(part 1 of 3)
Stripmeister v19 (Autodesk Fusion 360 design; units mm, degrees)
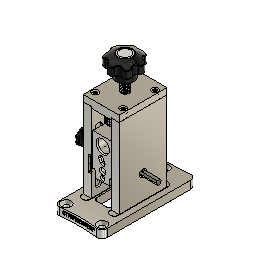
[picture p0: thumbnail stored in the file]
sketch "Sketch1" plane through (0, 0, 0) normal (0, 0, 1) x axis (1, 0, 0)
  line L1 (-38.1, -74.8109) -> (38.1, -74.8109)
  line L2 (-38.1, 74.8109) -> (-38.1, -74.8109)
  line L3 (38.1, 74.8109) -> (-38.1, 74.8109)
  line L4 (38.1, -74.8109) -> (38.1, 74.8109)
  line L5 (-38.1, 74.8109) -> (38.1, -74.8109)
  line L6 (38.1, 74.8109) -> (-38.1, -74.8109)
  line L7 (0, -74.8109) -> (0, 74.8109)
  line L8 (22.225, -74.8109) -> (22.225, 74.8109)
  line L9 (22.225, 0) -> (0, 0)
  line L10 (15.621, -39.4335) -> (15.621, 39.4335)
  line L11 (28.829, 39.4335) -> (28.829, -39.4335)
  line L12 (22.225, -46.0375) -> (22.225, 46.0375)
  line L13 (16.6687, -29.3687) -> (16.6688, 29.3687)
  line L14 (27.7813, 29.3687) -> (27.7813, -29.3688)
  line L15 (22.225, -34.925) -> (22.225, 34.925)
  line L16 (-28.829, 39.4335) -> (-28.829, -39.4335)
  line L17 (-27.7813, 29.3688) -> (-27.7813, -29.3688)
  line L18 (-16.6687, -29.3687) -> (-16.6688, 29.3687)
  line L19 (-15.621, -39.4335) -> (-15.621, 39.4335)
  line L20 (-12.7, 4.1513) -> (12.7, 4.1513)
  line L21 (-12.7, -37.5047) -> (-12.7, 4.1513)
  line L22 (12.7, -37.5047) -> (-12.7, -37.5047)
  line L23 (12.7, 4.1513) -> (12.7, -37.5047)
  line L24 (-12.7, -37.5047) -> (12.7, 4.1513)
  line L25 (12.7, -37.5047) -> (-12.7, 4.1513)
  line L26 (5.08, 10.8982) -> (0, 10.8982)
  line L27 (-3.175, 8.5169) -> (3.175, 8.5169)
  line L28 (-6.35, 18.0419) -> (-6.35, 11.6919)
  line L29 (3.175, 21.2169) -> (-3.175, 21.2169)
  line L30 (6.35, 11.6919) -> (6.35, 18.0419)
  line L31 (-6.35, 21.2169) -> (6.35, 8.5169)
  line L32 (6.35, 21.2169) -> (-6.35, 8.5169)
  circle C1 centre (22.225, 25.4) radius 3.9687
  circle C2 centre (22.225, -25.4) radius 3.9687
  circle C3 centre (-22.225, 25.4) radius 3.9687
  circle C4 centre (-22.225, -25.4) radius 3.9687
  arc A1 centre (22.225, -39.4335) radius 6.604 clockwise from (28.829, -39.4335) to (15.621, -39.4335)
  arc A2 centre (22.225, 39.4335) radius 6.604 clockwise from (15.621, 39.4335) to (28.829, 39.4335)
  arc A3 centre (22.225, -29.3688) radius 5.5563 clockwise from (27.7813, -29.3688) to (16.6687, -29.3687)
  arc A4 centre (22.225, 29.3687) radius 5.5563 clockwise from (16.6688, 29.3687) to (27.7813, 29.3687)
  arc A5 centre (-22.225, 39.4335) radius 6.604 clockwise from (-28.829, 39.4335) to (-15.621, 39.4335)
  arc A6 centre (-22.225, 29.3687) radius 5.5562 clockwise from (-27.7813, 29.3688) to (-16.6688, 29.3687)
  arc A7 centre (-22.225, -39.4335) radius 6.604 clockwise from (-15.621, -39.4335) to (-28.829, -39.4335)
  arc A8 centre (-22.225, -29.3688) radius 5.5562 clockwise from (-16.6687, -29.3687) to (-27.7813, -29.3688)
  circle C5 centre (-22.225, -25.4) radius 3.9687
  circle C6 centre (-22.225, 25.4) radius 3.9687
  circle C7 centre (28.575, 65.2859) radius 4.7625
  circle C8 centre (-28.575, 65.2859) radius 4.7625
  circle C9 centre (28.575, -65.2859) radius 3.9687
  circle C10 centre (-28.575, -65.2859) radius 3.9687
  circle C11 centre (0, 14.8669) radius 3.9688
  arc A9 centre (3.175, 11.6919) radius 3.175 clockwise from (6.35, 11.6919) to (3.175, 8.5169)
  arc A10 centre (-3.175, 11.6919) radius 3.175 clockwise from (-3.175, 8.5169) to (-6.35, 11.6919)
  arc A11 centre (-3.175, 18.0419) radius 3.175 clockwise from (-6.35, 18.0419) to (-3.175, 21.2169)
  arc A12 centre (3.175, 18.0419) radius 3.175 clockwise from (3.175, 21.2169) to (6.35, 18.0419)
  circle C12 centre (0, 62.4919) radius 3.9687
  point P6 (0, 0)
  point P1 (0, 0)
  point P7 (0, 74.8109)
  point P8 (0, -74.8109)
  point P9 (22.225, 74.8109)
  point P10 (22.225, -74.8109)
  point P11 (22.225, 25.4)
  point P12 (22.225, -25.4)
  point P13 (0, 0)
  point P14 (22.225, 0)
  point P23 (22.225, 46.0375)
  point P24 (22.225, -46.0375)
  point P31 (22.225, 34.925)
  point P32 (22.225, -34.925)
  point P17 (15.621, 39.4335)
  point P35 (-15.621, 39.4335)
  point P18 (15.621, -39.4335)
  point P42 (-15.621, -39.4335)
  point P19 (28.829, -39.4335)
  point P36 (-28.829, -39.4335)
  point P20 (28.829, 39.4335)
  point P34 (-28.829, 39.4335)
  point P25 (16.6688, 29.3687)
  point P40 (-16.6688, 29.3687)
  point P26 (16.6687, -29.3687)
  point P41 (-16.6687, -29.3687)
  point P27 (27.7813, -29.3688)
  point P37 (-27.7813, -29.3688)
  point P28 (27.7813, 29.3687)
  point P38 (-27.7813, 29.3688)
  point P51 (0, -16.6767)
  point P56 (0, 10.8982)
  point P58 (0, 14.8669)
  point P63 (0, 14.8669)
  point P59 (6.35, 8.5169)
  point P60 (-6.35, 8.5169)
  point P61 (-6.35, 21.2169)
  point P62 (6.35, 21.2169)
  point P76 (0, 62.4919)
  point P4 (-38.1, 74.8109)
  point P5 (38.1, 74.8109)
  point P3 (-38.1, -74.8109)
  point P49 (-12.7, -37.5047)
  point P50 (12.7, -37.5047)
  point P48 (-12.7, 4.1513)
  point P54 (28.575, -65.2859)
  point P52 (28.575, 65.2859)
  horizontal L1
  perpendicular L1 L2
  parallel L1 L3
  parallel L2 L4
  coincident L5 P6
  coincident L6 P6
  coincident P1 P6
  midpoint L3 P7
  midpoint L1 P8
  coincident L3 P9
  coincident L1 P10
  perpendicular L1 L8
  coincident L8 P11
  coincident L8 P12
  coincident P1 P13
  midpoint L8 P14
  symmetric L7 C1 C3
  symmetric L7 C2 C4
  tangent L10 A1
  tangent A1 L11
  parallel L10 L11
  tangent L11 A2
  tangent L10 A2
  midpoint A2 P23
  midpoint A1 P24
  coincident L8 P24
  parallel L8 L12
  midpoint P14 L12
  tangent L13 A3
  tangent A3 L14
  parallel L13 L14
  tangent L14 A4
  tangent L13 A4
  midpoint A4 P31
  midpoint A3 P32
  parallel L12 L15
  coincident L12 P31
  midpoint P14 L15
  symmetric L7 C1 C6
  symmetric L7 C2 C5
  symmetric L7 P17 P35
  symmetric L7 P18 P42
  symmetric L7 P19 P36
  symmetric L7 P20 P34
  symmetric L7 A1 A7
  symmetric L7 A2 A5
  symmetric L7 P25 P40
  symmetric L7 P26 P41
  symmetric L7 P27 P37
  symmetric L7 P28 P38
  symmetric L7 A3 A8
  symmetric L7 A4 A6
  horizontal L20
  perpendicular L20 L21
  parallel L20 L22
  parallel L21 L23
  coincident L24 P51
  coincident L25 P51
  coincident L7 P51
  symmetric L7 C7 C8
  symmetric L7 C9 C10
  coincident L7 P56
  perpendicular L7 L26
  coincident L7 P58
  tangent L26 C11
  horizontal L27
  perpendicular L27 L28
  parallel L27 L29
  parallel L28 L30
  coincident L31 P63
  coincident L32 P63
  coincident P58 P63
  coincident P59 L30
  coincident P59 L27
  tangent L30 A9
  tangent L27 A9
  coincident P60 L27
  coincident P60 L28
  tangent L27 A10
  tangent L28 A10
  equal A9 A10
  coincident P61 L28
  coincident P61 L29
  tangent L28 A11
  tangent L29 A11
  equal A9 A11
  coincident P62 L29
  coincident P62 L30
  tangent L29 A12
  tangent L30 A12
  equal A9 A12
  coincident L7 P76
  dimension "d1" distance P4 P5 = 76.2
  dimension "d2" distance P3 P4 = 149.6219 (= "5 57/64")
  dimension "d3" diameter C1 = 7.9375 (= "( 5 / 16 ) * 1 in")
  dimension "d4" diameter C2 = 7.9375 (= "( 5 / 16 ) * 1 in")
  dimension "d5" distance P11 L9 = 25.4
  dimension "d6" distance P12 L9 = 25.4
  dimension "d7" distance L7 P11 = 22.225 (= "( 1.75 / 2 ) * 1 in")
  dimension "d8" diameter A1 = 13.208
  dimension "d9" distance P23 P24 = 92.075
  dimension "d10" distance P31 P32 = 69.85
  dimension "d11" diameter A3 = 11.1125
  dimension "d12" distance P49 P50 = 25.4
  dimension "d13" distance P48 P49 = 41.656
  dimension "d14" distance L1 L22 = 37.3062 (= "1 15/32")
  dimension "d16" diameter C7 = 9.525 (= "( 3 / 8 ) * 1 in")
  dimension "d17" diameter C9 = 7.9375
  dimension "d18" distance L4 P54 = 9.525 (= "( 3 / 8 ) * 1 in")
  dimension "d19" distance L1 P54 = 9.525 (= "( 3 / 8 ) * 1 in")
  dimension "d20" distance L3 P52 = 9.525 (= "( 3 / 8 ) * 1 in")
  dimension "d21" distance L4 P52 = 9.525 (= "( 3 / 8 ) * 1 in")
  dimension "d22" distance L20 L26 = 6.7469 (= "( 17 / 64 ) * 1 in")
  dimension "d23" diameter C11 = 7.9375 (= "( 5 / 16 ) * 1 in")
  dimension "d24" distance P61 P62 = 12.7
  dimension "d25" distance P60 P61 = 12.7
  dimension "d26" radius A9 = 3.175
  dimension "d27" diameter C12 = 7.9375 (= "( 5 / 16 ) * 1 in")
  dimension "d28" distance P58 P76 = 47.625 (= "1 7/8")
extrude "Extrude1" new body sketch "Sketch1" profile of L1 L2 L3 L4 C1 C2 C3 C4 L10 A1 L11 A2 L13 A3 L14 A4 A5 L16 L17 A6 L18 L19 A7 A8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 against normal blind 12.7
extrude "Extrude2" cut sketch "Sketch1" profile of C1 C2 C3 C4 L13 A3 L14 A4 L17 A6 L18 A8 C5 C6 against normal blind 2.3813 (magnitude of "( -3 / 32 ) * 1 in")
extrude "Extrude3" cut sketch "Sketch1" profile of L10 A1 L11 A2 L13 A3 L14 A4 A5 L16 L17 A6 L18 L19 A7 A8 against normal blind 0.3969 (magnitude of "( -1 / 64 ) * 1 in")
chamfer "Chamfer1" distance 3.81
extrude "Extrude4" cut sketch "Sketch1" profile of C11 L27 L28 L29 L30 A9 A10 A11 A12 against normal blind 4.3656 (magnitude of "( -11 / 64 ) * 1 in")
fillet "Fillet1" radius 7.9375 (= "( 5 / 16 ) * 1 in")
fillet "Fillet2" radius 4.7625
sketch "Sketch1" plane through (0, 0, 0) normal (0, 0, 1) x axis (-1, 0, 0)
  line L1 (-6.35, -11.6919) -> (-6.35, -18.0419)
  line L2 (3.175, -8.5169) -> (-3.175, -8.5169)
  line L3 (6.35, -18.0419) -> (6.35, -11.6919)
  line L4 (-3.175, -21.2169) -> (3.175, -21.2169)
  line L5 (38.1, 66.8734) -> (38.1, -66.8734)
  line L6 (-30.1625, 74.8109) -> (30.1625, 74.8109)
  line L7 (-38.1, -66.8734) -> (-38.1, 66.8734)
  line L8 (30.1625, -74.8109) -> (-30.1625, -74.8109)
  line L9 (-12.7, 32.7422) -> (-12.7, 0.6112)
  line L10 (7.9375, 37.5047) -> (-7.9375, 37.5047)
  line L11 (12.7, 0.6112) -> (12.7, 32.7422)
  line L12 (-7.9375, -4.1513) -> (7.9375, -4.1513)
  line L13 (-15.621, -39.4335) -> (-15.621, 39.4335)
  line L14 (-28.829, 39.4335) -> (-28.829, -39.4335)
  line L15 (28.829, -39.4335) -> (28.829, 39.4335)
  line L16 (15.621, 39.4335) -> (15.621, -39.4335)
  line L17 (-6.35, -18.0419) -> (-6.35, -11.6919)
  line L18 (3.175, -21.2169) -> (-3.175, -21.2169)
  line L19 (6.35, -11.6919) -> (6.35, -18.0419)
  line L20 (-3.175, -8.5169) -> (3.175, -8.5169)
  arc A1 centre (-3.175, -11.6919) radius 3.175 clockwise from (-6.35, -11.6919) to (-3.175, -8.5169)
  arc A2 centre (3.175, -11.6919) radius 3.175 clockwise from (3.175, -8.5169) to (6.35, -11.6919)
  arc A3 centre (3.175, -18.0419) radius 3.175 clockwise from (6.35, -18.0419) to (3.175, -21.2169)
  arc A4 centre (-3.175, -18.0419) radius 3.175 clockwise from (-3.175, -21.2169) to (-6.35, -18.0419)
  circle C1 centre (-28.575, 65.2859) radius 7.7787
  arc A5 centre (30.1625, -66.8734) radius 7.9375 clockwise from (38.1, -66.8734) to (30.1625, -74.8109)
  arc A6 centre (30.1625, 66.8734) radius 7.9375 clockwise from (30.1625, 74.8109) to (38.1, 66.8734)
  arc A7 centre (-30.1625, 66.8734) radius 7.9375 clockwise from (-38.1, 66.8734) to (-30.1625, 74.8109)
  arc A8 centre (-30.1625, -66.8734) radius 7.9375 clockwise from (-30.1625, -74.8109) to (-38.1, -66.8734)
  arc A9 centre (-7.9375, 32.7422) radius 4.7625 clockwise from (-12.7, 32.7422) to (-7.9375, 37.5047)
  arc A10 centre (7.9375, 32.7422) radius 4.7625 clockwise from (7.9375, 37.5047) to (12.7, 32.7422)
  arc A11 centre (7.9375, 0.6112) radius 4.7625 clockwise from (12.7, 0.6112) to (7.9375, -4.1513)
  arc A12 centre (-7.9375, 0.6112) radius 4.7625 clockwise from (-7.9375, -4.1513) to (-12.7, 0.6112)
  arc A13 centre (-22.225, -39.4335) radius 6.604 clockwise from (-15.621, -39.4335) to (-28.829, -39.4335)
  arc A14 centre (-22.225, 39.4335) radius 6.604 clockwise from (-28.829, 39.4335) to (-15.621, 39.4335)
  arc A15 centre (22.225, -39.4335) radius 6.604 clockwise from (28.829, -39.4335) to (15.621, -39.4335)
  arc A16 centre (22.225, 39.4335) radius 6.604 clockwise from (15.621, 39.4335) to (28.829, 39.4335)
  circle C2 centre (0, -62.4919) radius 7.7787
  circle C3 centre (28.575, 65.2859) radius 7.7787
  circle C4 centre (0, -14.8669) radius 3.9687
  arc A17 centre (-3.175, -11.6919) radius 3.175 clockwise from (-6.35, -11.6919) to (-3.175, -8.5169)
  arc A18 centre (-3.175, -18.0419) radius 3.175 clockwise from (-3.175, -21.2169) to (-6.35, -18.0419)
  arc A19 centre (3.175, -18.0419) radius 3.175 clockwise from (6.35, -18.0419) to (3.175, -21.2169)
  arc A20 centre (3.175, -11.6919) radius 3.175 clockwise from (3.175, -8.5169) to (6.35, -11.6919)
  circle C5 centre (0, -14.8669) radius 9.3266
  concentric C4 C5
  dimension "d42" diameter C5 = 18.6531 (= "( 47 / 64 ) * 1 in")
extrude "Extrude1" new body sketch "Sketch1" profile of L1 A1 L2 A2 L3 A3 L4 A4 C4 A17 L17 A18 L18 A19 L19 A20 L20 to an object
extrude "Extrude2" add sketch "Sketch1" profile of L1 A1 L2 A2 L3 A3 L4 A4 C4 A17 L17 A18 L18 A19 L19 A20 L20 C5 along normal blind 38.608
extrude "Extrude3" add sketch "Sketch1" profile of C4 against normal blind 4.3688
extrude "Extrude4" cut of existing geometry blind 0
extrude "Extrude5" add sketch "Sketch1" profile of L1 A1 L2 A2 L3 A3 L4 A4 C4 A17 L17 A18 L18 A19 L19 A20 L20 against normal blind 4.3688
extrude "Extrude6" sketch "Sketch1" profile of C4 blind 15.875 (= "( 5 / 8 ) * 1 in")
sketch "Sketch2" plane through (0, 0, 38.608) normal (0, 0, 1) x axis (-1, 0, 0)
  line L1 (-9.144, -16.7032) -> (9.144, -16.7032)
  line L2 (0, -5.5404) -> (0, -16.7032)
  circle C1 centre (0, -14.8669) radius 9.3266
  arc A1 centre (-16.0599, -1.7116) radius 16.51 clockwise from (0, -5.5404) to (-9.144, -16.7032)
  arc A2 centre (16.0599, -1.7116) radius 16.51 clockwise from (9.144, -16.7032) to (0, -5.5404)
  point P3 (9.144, -16.7032)
  point P4 (-9.144, -16.7032)
  point P5 (0, -16.7032)
  point P6 (0, -5.5404)
  point P9 (9.144, -16.7032)
  point P10 (0, -5.5404)
  coincident C1 P3
  coincident C1 P4
  horizontal L1
  midpoint L1 P5
  coincident C1 P6
  perpendicular L1 L2
  symmetric P4 L2 P9
  symmetric P6 L2 P10
  symmetric L2 A1 A2
  dimension "d57" distance P3 P4 = 18.288
  dimension "d58" radius A1 = 16.51
extrude "Extrude7" cut sketch "Sketch2" profile of C1 A1 A2 against normal blind 12.7
sketch "Sketch3" plane through (0, 0, 38.608) normal (0, 0, 1) x axis (-1, 0, 0)
  arc A1 centre (16.0599, -1.7116) radius 16.51 clockwise from (9.144, -16.7032) to (0, -5.5404)
  arc A2 centre (-16.0599, -1.7116) radius 16.51 clockwise from (0, -5.5404) to (-9.144, -16.7032)
  arc A3 centre (0, -14.8669) radius 9.3266 clockwise from (9.144, -16.7032) to (-9.144, -16.7032)
  arc A4 centre (0, -14.8669) radius 9.3266 clockwise from (9.144, -16.7032) to (-9.144, -16.7032)
  arc A5 centre (0, -14.8669) radius 9.3266 clockwise from (-9.144, -16.7032) to (0, -5.5404)
  arc A6 centre (0, -14.8669) radius 9.3266 clockwise from (0, -5.5404) to (9.144, -16.7032)
  circle C1 centre (0, -14.8669) radius 9.3266
  arc A7 centre (0, -14.8669) radius 9.1996 clockwise from (9.0195, -16.6782) to (-9.0195, -16.6782)
  arc A8 centre (0, -14.8669) radius 9.1996 clockwise from (0, -5.6674) to (9.0195, -16.6782)
  arc A9 centre (0, -14.8669) radius 9.1996 clockwise from (-9.0195, -16.6782) to (0, -5.6674)
  dimension "d61" = -0.127
extrude "Extrude8" cut sketch "Sketch3" blind -0.635 from offset -20.9677
fillet "Fillet1" radius 0.254
thread "Thread1"
sketch "Sketch2" plane through (0, 0, -12.7) normal (0, 0, -1) x axis (1, 0, 0)
  line L1 (30.1625, -74.8109) -> (-30.1625, -74.8109)
  line L2 (38.1, 66.8734) -> (38.1, -66.8734)
  line L3 (-30.1625, 74.8109) -> (30.1625, 74.8109)
  line L4 (-38.1, -66.8734) -> (-38.1, 66.8734)
  line L5 (12.7, 0.6112) -> (12.7, 32.7422)
  line L6 (-7.9375, -4.1513) -> (7.9375, -4.1513)
  line L7 (-12.7, 32.7422) -> (-12.7, 0.6112)
  line L8 (7.9375, 37.5047) -> (-7.9375, 37.5047)
  arc A1 centre (-30.1625, -66.8734) radius 7.9375 clockwise from (-30.1625, -74.8109) to (-38.1, -66.8734)
  arc A2 centre (30.1625, -66.8734) radius 7.9375 clockwise from (38.1, -66.8734) to (30.1625, -74.8109)
  arc A3 centre (30.1625, 66.8734) radius 7.9375 clockwise from (30.1625, 74.8109) to (38.1, 66.8734)
  arc A4 centre (-30.1625, 66.8734) radius 7.9375 clockwise from (-38.1, 66.8734) to (-30.1625, 74.8109)
  circle C1 centre (-22.225, -25.4) radius 3.9687
  circle C2 centre (28.575, 65.2859) radius 3.9687
  circle C3 centre (-22.225, 25.4) radius 3.9687
  circle C4 centre (0, -14.8669) radius 3.9687
  circle C5 centre (-28.575, 65.2859) radius 3.9687
  circle C6 centre (0, -62.4919) radius 3.9687
  circle C7 centre (22.225, -25.4) radius 3.9688
  circle C8 centre (22.225, 25.4) radius 3.9687
  arc A5 centre (7.9375, 0.6112) radius 4.7625 clockwise from (12.7, 0.6112) to (7.9375, -4.1513)
  arc A6 centre (-7.9375, 0.6112) radius 4.7625 clockwise from (-7.9375, -4.1513) to (-12.7, 0.6112)
  arc A7 centre (-7.9375, 32.7422) radius 4.7625 clockwise from (-12.7, 32.7422) to (-7.9375, 37.5047)
  arc A8 centre (7.9375, 32.7422) radius 4.7625 clockwise from (7.9375, 37.5047) to (12.7, 32.7422)
  circle C9 centre (22.225, 25.4) radius 5.1594
  circle C10 centre (22.225, -25.4) radius 5.1594
  circle C11 centre (-22.225, -25.4) radius 5.1594
  circle C12 centre (-22.225, 25.4) radius 5.1594
  circle C13 centre (0, -14.8669) radius 5.1594
  concentric C8 C9
  concentric C7 C10
  concentric C1 C11
  concentric C3 C12
  concentric C4 C13
  dimension "d67" diameter C9 = 10.3188 (= "( 13 / 32 ) * 1 in")
  dimension "d68" diameter C10 = 10.3188 (= "( 13 / 32 ) * 1 in")
  dimension "d69" diameter C11 = 10.3188 (= "( 13 / 32 ) * 1 in")
  dimension "d70" diameter C12 = 10.3188 (= "( 13 / 32 ) * 1 in")
  dimension "d71" diameter C13 = 10.3188 (= "( 13 / 32 ) * 1 in")
extrude "Extrude5" cut sketch "Sketch2" profile of C1 C3 C4 C7 C8 C9 C10 C11 C12 C13 against normal blind 4.7625 (magnitude of "( -3 / 16 ) * 1 in")
base_feature "Base Feature1"
position "Position1"
copy_paste_bodies "CopyPasteBodies1"
move "Move1"
copy_paste_bodies "CopyPasteBodies2"
move "Move2"
copy_paste_bodies "CopyPasteBodies3"
move "Move3"
align "Align1"
align "Align2"
align "Align3"
align "Align4"
sketch "Sketch1" plane through (0, 0, 0) normal (0, 0, 1) x axis (-1, 0, 0)
  line L1 (-6.35, -11.6919) -> (-6.35, -18.0419)
  line L2 (3.175, -8.5169) -> (-3.175, -8.5169)
  line L3 (6.35, -18.0419) -> (6.35, -11.6919)
  line L4 (-3.175, -21.2169) -> (3.175, -21.2169)
  line L5 (38.1, 66.8734) -> (38.1, -66.8734)
  line L6 (-30.1625, 74.8109) -> (30.1625, 74.8109)
  line L7 (-38.1, -66.8734) -> (-38.1, 66.8734)
  line L8 (30.1625, -74.8109) -> (-30.1625, -74.8109)
  line L9 (-12.7, 32.7422) -> (-12.7, 0.6112)
  line L10 (7.9375, 37.5047) -> (-7.9375, 37.5047)
  line L11 (12.7, 0.6112) -> (12.7, 32.7422)
  line L12 (-7.9375, -4.1513) -> (7.9375, -4.1513)
  line L13 (-15.621, -39.4335) -> (-15.621, 39.4335)
  line L14 (-28.829, 39.4335) -> (-28.829, -39.4335)
  line L15 (28.829, -39.4335) -> (28.829, 39.4335)
  line L16 (15.621, 39.4335) -> (15.621, -39.4335)
  line L17 (27.7813, 29.3688) -> (27.7813, -29.3687)
  line L18 (16.6688, -29.3687) -> (16.6688, 29.3687)
  line L19 (22.225, -25.4) -> (22.225, 25.4)
  line L20 (15.875, -38.1) -> (28.575, -38.1)
  line L21 (15.875, 38.1) -> (15.875, -38.1)
  line L22 (28.575, 38.1) -> (15.875, 38.1)
  line L23 (28.575, -38.1) -> (28.575, 38.1)
  line L24 (15.875, 38.1) -> (28.575, -38.1)
  line L25 (28.575, 38.1) -> (15.875, -38.1)
  arc A1 centre (-3.175, -11.6919) radius 3.175 clockwise from (-6.35, -11.6919) to (-3.175, -8.5169)
  arc A2 centre (3.175, -11.6919) radius 3.175 clockwise from (3.175, -8.5169) to (6.35, -11.6919)
  arc A3 centre (3.175, -18.0419) radius 3.175 clockwise from (6.35, -18.0419) to (3.175, -21.2169)
  arc A4 centre (-3.175, -18.0419) radius 3.175 clockwise from (-3.175, -21.2169) to (-6.35, -18.0419)
  circle C1 centre (-28.575, 65.2859) radius 7.7787
  arc A5 centre (30.1625, -66.8734) radius 7.9375 clockwise from (38.1, -66.8734) to (30.1625, -74.8109)
  arc A6 centre (30.1625, 66.8734) radius 7.9375 clockwise from (30.1625, 74.8109) to (38.1, 66.8734)
  arc A7 centre (-30.1625, 66.8734) radius 7.9375 clockwise from (-38.1, 66.8734) to (-30.1625, 74.8109)
  arc A8 centre (-30.1625, -66.8734) radius 7.9375 clockwise from (-30.1625, -74.8109) to (-38.1, -66.8734)
  arc A9 centre (-7.9375, 32.7422) radius 4.7625 clockwise from (-12.7, 32.7422) to (-7.9375, 37.5047)
  arc A10 centre (7.9375, 32.7422) radius 4.7625 clockwise from (7.9375, 37.5047) to (12.7, 32.7422)
  arc A11 centre (7.9375, 0.6112) radius 4.7625 clockwise from (12.7, 0.6112) to (7.9375, -4.1513)
  arc A12 centre (-7.9375, 0.6112) radius 4.7625 clockwise from (-7.9375, -4.1513) to (-12.7, 0.6112)
  arc A13 centre (-22.225, -39.4335) radius 6.604 clockwise from (-15.621, -39.4335) to (-28.829, -39.4335)
  arc A14 centre (-22.225, 39.4335) radius 6.604 clockwise from (-28.829, 39.4335) to (-15.621, 39.4335)
  arc A15 centre (22.225, -39.4335) radius 6.604 clockwise from (28.829, -39.4335) to (15.621, -39.4335)
  arc A16 centre (22.225, 39.4335) radius 6.604 clockwise from (15.621, 39.4335) to (28.829, 39.4335)
  circle C2 centre (0, -62.4919) radius 7.7787
  circle C3 centre (28.575, 65.2859) radius 7.7787
  circle C4 centre (22.225, -25.4) radius 3.9687
  circle C5 centre (22.225, 25.4) radius 3.9687
  arc A17 centre (22.225, -29.3687) radius 5.5562 clockwise from (27.7813, -29.3687) to (16.6688, -29.3687)
  arc A18 centre (22.225, 29.3688) radius 5.5562 clockwise from (16.6688, 29.3687) to (27.7813, 29.3688)
  point P54 (22.225, 25.4)
  point P61 (22.225, 25.4)
  point P53 (22.225, -25.4)
  point P62 (22.225, -25.4)
  point P67 (22.225, 0)
  point P65 (15.875, 38.1)
  point P66 (28.575, 38.1)
  point P64 (15.875, -38.1)
  coincident P54 P61
  coincident P53 P62
  horizontal L20
  perpendicular L20 L21
  parallel L20 L22
  parallel L21 L23
  coincident L24 P67
  coincident L25 P67
  midpoint L19 P67
  dimension "d74" distance P65 P66 = 12.7
  dimension "d75" distance P64 P65 = 76.2
extrude "Extrude1" new body sketch "Sketch1" profile of C4 C5 A17 L17 A18 L18 to an object
extrude "Extrude2" add sketch "Sketch1" profile of C4 C5 A17 L17 A18 L18 L20 L21 L22 L23 along normal blind 127
extrude "Extrude3" cut sketch "Sketch1" profile of C4 C5 along normal blind 16.129
sketch "Sketch2" plane through (0, 0, 127) normal (0, 0, 1) x axis (-1, 0, 0)
  line L1 (15.875, 38.1) -> (28.575, 38.1)
  line L2 (15.875, -38.1) -> (15.875, 38.1)
  line L3 (28.575, -38.1) -> (15.875, -38.1)
  line L4 (28.575, 38.1) -> (28.575, -38.1)
  circle C1 centre (22.225, 25.4) radius 3.9687
  circle C2 centre (22.225, -25.4) radius 3.9687
  circle C3 centre (22.225, -25.4) radius 5.5245
  circle C4 centre (22.225, 25.4) radius 5.5245
  concentric C2 C3
  concentric C1 C4
  dimension "d83" diameter C3 = 11.049
  dimension "d84" diameter C4 = 11.049
extrude "Extrude4" add sketch "Sketch2" profile of C1 C2 C3 C4 along normal blind 1.778
extrude "Extrude5" of existing geometry blind -16.129
thread "Thread1"
fillet "Fillet1" radius 1.27
align "Align1"
sketch "Sketch3" plane through (15.875, 0, 0) normal (-1, 0, 0) x axis (0, -1, 0)
  line L1 (38.1, 0) -> (-38.1, 0)
  line L2 (38.1, 127) -> (38.1, 0)
  line L3 (-38.1, 127) -> (38.1, 127)
  line L4 (-38.1, 0) -> (-38.1, 127)
  line L5 (20.574, 15.748) -> (20.574, 93.472)
  line L6 (31.75, 93.472) -> (31.75, 15.748)
  line L7 (26.162, 10.16) -> (26.162, 99.06)
  line L8 (38.1, 52.6923) -> (-38.1, 52.6923)
  line L9 (0, 52.6923) -> (0, 127)
  line L10 (5.588, 58.2803) -> (0, 58.2803)
  line L11 (-5.588, 58.2803) -> (0, 58.2803)
  line L12 (-5.588, 127) -> (-5.588, 58.2803)
  line L13 (5.588, 127) -> (5.588, 58.2803)
  line L14 (6.096, 127) -> (-6.096, 127)
  line L15 (5.588, 116.84) -> (-5.588, 116.84)
  line L16 (-5.588, 116.84) -> (-6.096, 127)
  line L17 (5.588, 116.84) -> (6.096, 127)
  line L18 (0, 0) -> (0, 58.2803)
  line L19 (0, 10.16) -> (38.1, 10.16)
  arc A1 centre (26.162, 15.748) radius 5.588 clockwise from (31.75, 15.748) to (20.574, 15.748)
  arc A2 centre (26.162, 93.472) radius 5.588 clockwise from (20.574, 93.472) to (31.75, 93.472)
  circle C1 centre (0, 58.2803) radius 5.588
  circle C2 centre (0, 38.1) radius 11.43
  circle C3 centre (0, 38.1) radius 5.8674
  point P12 (26.162, 99.06)
  point P13 (26.162, 10.16)
  point P14 (-38.1, 52.6923)
  point P15 (38.1, 52.6923)
  point P16 (0, 127)
  point P17 (0, 52.6923)
  point P18 (0, 58.2803)
  point P19 (0, 58.2803)
  point P20 (5.588, 58.2803)
  point P21 (0, 58.2803)
  point P22 (-5.588, 58.2803)
  point P23 (-5.588, 127)
  point P24 (5.588, 127)
  point P27 (-5.588, 116.84)
  point P28 (5.588, 116.84)
  point P29 (0, 58.2803)
  point P1 (0, 0)
  point P30 (0, 0)
  point P31 (0, 38.1)
  point P32 (38.1, 10.16)
  point P33 (0, 10.16)
  point P25 (-6.096, 127)
  point P26 (6.096, 127)
  tangent L5 A1
  tangent A1 L6
  parallel L5 L6
  tangent L6 A2
  tangent L5 A2
  midpoint A2 P12
  midpoint A1 P13
  parallel L2 L7
  coincident L4 P14
  coincident L2 P15
  perpendicular L2 L8
  midpoint L3 P16
  midpoint L8 P17
  coincident L9 P18
  tangent L8 C1
  coincident P18 P19
  coincident C1 P20
  perpendicular L9 L10
  coincident P18 P21
  coincident C1 P22
  perpendicular L9 L11
  coincident L3 P23
  tangent C1 L12
  coincident L3 P24
  tangent C1 L13
  perpendicular L13 L14
  midpoint P16 L14
  coincident L12 P27
  coincident L13 P28
  perpendicular L13 L15
  coincident P18 P29
  coincident P1 P30
  coincident L18 P31
  coincident L2 P32
  coincident L18 P33
  perpendicular L18 L19
  tangent A1 L19
  concentric C2 C3
  dimension "d92" diameter A1 = 11.176
  dimension "d93" distance L3 L8 = 74.3077
  dimension "d94" diameter C1 = 11.176
  dimension "d95" distance P25 P26 = 12.192
  dimension "d96" distance L14 L15 = 10.16
  dimension "d97" distance P1 P31 = 38.1
  dimension "d98" diameter C2 = 22.86
  dimension "d99" distance L2 L6 = 6.35
  dimension "d100" distance L1 L19 = 10.16
  dimension "d101" diameter C3 = 11.7348
extrude "Extrude6" cut sketch "Sketch3" profile of L3 L5 A1 L6 A2 C1 L12 L13 L16 L17 against normal blind 3.175 (magnitude of "( -1 / 8 ) * 1 in")
extrude "Extrude7" cut sketch "Sketch3" profile of C3 against normal blind 12.7
extrude "Extrude8" cut sketch "Sketch3" profile of C2 C3 against normal blind 7.9375
fillet "Fillet2" radius 1.27
mirror "Mirror1" mirrorStitchTolerance 0.1016
copy_paste_bodies "CutPasteBodies"
component_from_bodies "Body->Comp"
delete_face "DeleteFace1"
base_feature "Base Feature1"
offset_faces "OffsetFaces1" distance 0.381
base_feature "Base Feature1"
position "Position2"
position "Position3"
sketch "Sketch1" plane through (-15.875, 0, 0) normal (1, 0, 0) x axis (0, 1, 0)
  line L1 (5.588, 116.84) -> (6.0357, 125.7934)
  line L2 (5.588, 58.2803) -> (5.588, 116.84)
  line L3 (-5.588, 116.84) -> (-5.588, 58.2803)
  line L4 (-6.0357, 125.7934) -> (-5.588, 116.84)
  line L5 (-38.1, 127) -> (-7.3041, 127)
  line L6 (-38.1, 0) -> (-38.1, 127)
  line L7 (38.1, 0) -> (-38.1, 0)
  line L8 (38.1, 127) -> (38.1, 0)
  line L9 (7.3041, 127) -> (38.1, 127)
  line L10 (-20.574, 15.748) -> (-20.574, 93.472)
  line L11 (-31.75, 93.472) -> (-31.75, 15.748)
  line L12 (-11.475, 113.75) -> (-16.725, 113.75)
  line L13 (-16.725, 114.5) -> (-11.475, 114.5)
  line L14 (-11.1, 114.125) -> (-17.1, 114.125)
  line L15 (-17.1, 114.5) -> (-38.1, 114.5)
  line L16 (-17.1, 127) -> (-17.1, 114.5)
  line L17 (-11.475, 111.6333) -> (-16.725, 111.6333)
  line L18 (-16.725, 112.3833) -> (-11.475, 112.3833)
  line L19 (-11.475, 109.5167) -> (-16.725, 109.5167)
  line L20 (-16.725, 110.2667) -> (-11.475, 110.2667)
  line L21 (-11.475, 107.4) -> (-16.725, 107.4)
  line L22 (-16.725, 108.15) -> (-11.475, 108.15)
  line L23 (-11.475, 105.2833) -> (-16.725, 105.2833)
  line L24 (-16.725, 106.0333) -> (-11.475, 106.0333)
  line L25 (-11.475, 103.1667) -> (-16.725, 103.1667)
  line L26 (-16.725, 103.9167) -> (-11.475, 103.9167)
  line L27 (-11.475, 101.05) -> (-16.725, 101.05)
  line L28 (-16.725, 101.8) -> (-11.475, 101.8)
  line L29 (-11.475, 98.9333) -> (-16.725, 98.9333)
  line L30 (-16.725, 99.6833) -> (-11.475, 99.6833)
  line L31 (-11.475, 96.8167) -> (-16.725, 96.8167)
  line L32 (-16.725, 97.5667) -> (-11.475, 97.5667)
  line L33 (-11.475, 94.7) -> (-16.725, 94.7)
  line L34 (-16.725, 95.45) -> (-11.475, 95.45)
  line L35 (-11.475, 92.5833) -> (-16.725, 92.5833)
  line L36 (-16.725, 93.3333) -> (-11.475, 93.3333)
  line L37 (-11.475, 90.4667) -> (-16.725, 90.4667)
  line L38 (-16.725, 91.2167) -> (-11.475, 91.2167)
  line L39 (-11.475, 88.35) -> (-16.725, 88.35)
  line L40 (-16.725, 89.1) -> (-11.475, 89.1)
  circle C1 centre (0, 38.1) radius 11.049
  arc A1 centre (7.3041, 125.73) radius 1.27 clockwise from (6.0357, 125.7934) to (7.3041, 127)
  arc A2 centre (0, 58.2803) radius 5.588 clockwise from (5.588, 58.2803) to (-5.588, 58.2803)
  arc A3 centre (-7.3041, 125.73) radius 1.27 clockwise from (-7.3041, 127) to (-6.0357, 125.7934)
  arc A4 centre (-26.162, 15.748) radius 5.588 clockwise from (-20.574, 15.748) to (-31.75, 15.748)
  arc A5 centre (-26.162, 93.472) radius 5.588 clockwise from (-31.75, 93.472) to (-20.574, 93.472)
  arc A6 centre (-11.475, 114.125) radius 0.375 clockwise from (-11.475, 114.5) to (-11.475, 113.75)
  arc A7 centre (-16.725, 114.125) radius 0.375 clockwise from (-16.725, 113.75) to (-16.725, 114.5)
  arc A8 centre (-16.725, 112.0083) radius 0.375 clockwise from (-16.725, 111.6333) to (-16.725, 112.3833)
  arc A9 centre (-11.475, 112.0083) radius 0.375 clockwise from (-11.475, 112.3833) to (-11.475, 111.6333)
  arc A10 centre (-16.725, 109.8917) radius 0.375 clockwise from (-16.725, 109.5167) to (-16.725, 110.2667)
  arc A11 centre (-11.475, 109.8917) radius 0.375 clockwise from (-11.475, 110.2667) to (-11.475, 109.5167)
  arc A12 centre (-16.725, 107.775) radius 0.375 clockwise from (-16.725, 107.4) to (-16.725, 108.15)
  arc A13 centre (-11.475, 107.775) radius 0.375 clockwise from (-11.475, 108.15) to (-11.475, 107.4)
  arc A14 centre (-16.725, 105.6583) radius 0.375 clockwise from (-16.725, 105.2833) to (-16.725, 106.0333)
  arc A15 centre (-11.475, 105.6583) radius 0.375 clockwise from (-11.475, 106.0333) to (-11.475, 105.2833)
  arc A16 centre (-16.725, 103.5417) radius 0.375 clockwise from (-16.725, 103.1667) to (-16.725, 103.9167)
  arc A17 centre (-11.475, 103.5417) radius 0.375 clockwise from (-11.475, 103.9167) to (-11.475, 103.1667)
  arc A18 centre (-16.725, 101.425) radius 0.375 clockwise from (-16.725, 101.05) to (-16.725, 101.8)
  arc A19 centre (-11.475, 101.425) radius 0.375 clockwise from (-11.475, 101.8) to (-11.475, 101.05)
  arc A20 centre (-16.725, 99.3083) radius 0.375 clockwise from (-16.725, 98.9333) to (-16.725, 99.6833)
  arc A21 centre (-11.475, 99.3083) radius 0.375 clockwise from (-11.475, 99.6833) to (-11.475, 98.9333)
  arc A22 centre (-16.725, 97.1917) radius 0.375 clockwise from (-16.725, 96.8167) to (-16.725, 97.5667)
  arc A23 centre (-11.475, 97.1917) radius 0.375 clockwise from (-11.475, 97.5667) to (-11.475, 96.8167)
  arc A24 centre (-16.725, 95.075) radius 0.375 clockwise from (-16.725, 94.7) to (-16.725, 95.45)
  arc A25 centre (-11.475, 95.075) radius 0.375 clockwise from (-11.475, 95.45) to (-11.475, 94.7)
  arc A26 centre (-16.725, 92.9583) radius 0.375 clockwise from (-16.725, 92.5833) to (-16.725, 93.3333)
  arc A27 centre (-11.475, 92.9583) radius 0.375 clockwise from (-11.475, 93.3333) to (-11.475, 92.5833)
  arc A28 centre (-16.725, 90.8417) radius 0.375 clockwise from (-16.725, 90.4667) to (-16.725, 91.2167)
  arc A29 centre (-11.475, 90.8417) radius 0.375 clockwise from (-11.475, 91.2167) to (-11.475, 90.4667)
  arc A30 centre (-16.725, 88.725) radius 0.375 clockwise from (-16.725, 88.35) to (-16.725, 89.1)
  arc A31 centre (-11.475, 88.725) radius 0.375 clockwise from (-11.475, 89.1) to (-11.475, 88.35)
  point P30 (-17.1, 114.125)
  point P31 (-11.1, 114.125)
  point P32 (-38.1, 114.5)
  point P34 (-17.1, 127)
  point P33 (-17.1, 114.5)
  tangent L12 A6
  tangent A6 L13
  parallel L12 L13
  tangent L13 A7
  tangent L12 A7
  midpoint A7 P30
  midpoint A6 P31
  horizontal L14
  coincident L6 P32
  perpendicular L6 L15
  coincident L5 P34
  perpendicular L5 L16
  tangent A7 L16
  collinear L13 L15
  dimension "d113" diameter A6 = 0.75
  dimension "d114" distance P32 P33 = 21
  dimension "d115" distance P33 P34 = 12.5
  dimension "d116" distance P30 P31 = 6
  dimension "d119" R-Pattern1-uDistance = 0
  dimension "d120" R-Pattern1-vDistance = -25.4
extrude "Extrude1" cut sketch "Sketch1" profile of L12 A6 L13 A7 A8 L17 L18 A9 A10 L19 L20 A11 A12 L21 L22 A13 A14 L23 L24 A15 A16 L25 L26 A17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 against normal blind 0.25
sketch "Sketch1" plane through (0, 0, 127) normal (0, 0, 1) x axis (-1, 0, 0)
  line L1 (-19.05, 7.3041) -> (-19.05, -7.3041)
  line L2 (-15.875, 7.3041) -> (-19.05, 7.3041)
  line L3 (-15.875, 38.1) -> (-15.875, 7.3041)
  line L4 (-28.575, 38.1) -> (-15.875, 38.1)
  line L5 (-28.575, -38.1) -> (-28.575, 38.1)
  line L6 (-15.875, -38.1) -> (-28.575, -38.1)
  line L7 (-15.875, -7.3041) -> (-15.875, -38.1)
  line L8 (-19.05, -7.3041) -> (-15.875, -7.3041)
  line L9 (-30.1625, -74.8109) -> (30.1625, -74.8109)
  line L10 (-38.1, 66.8734) -> (-38.1, -66.8734)
  line L11 (30.1625, 74.8109) -> (-30.1625, 74.8109)
  line L12 (38.1, -66.8734) -> (38.1, 66.8734)
  line L13 (-12.7, 0.6112) -> (-12.7, 32.7422)
  line L14 (7.9375, -4.1513) -> (-7.9375, -4.1513)
  line L15 (12.7, 32.7422) -> (12.7, 0.6112)
  line L16 (-7.9375, 37.5047) -> (7.9375, 37.5047)
  line L17 (28.575, 38.1) -> (-28.575, 38.1)
  line L18 (28.575, -38.1) -> (28.575, 38.1)
  line L19 (-28.575, -38.1) -> (28.575, -38.1)
  line L20 (-28.575, 38.1) -> (-28.575, -38.1)
  line L21 (-15.875, -38.1) -> (-15.875, 38.1)
  line L22 (15.875, -38.1) -> (15.875, 38.1)
  line L23 (28.575, 0) -> (-28.575, 0)
  line L24 (0, -38.1) -> (0, 38.1)
  circle C1 centre (-22.225, 25.4) radius 5.5245
  circle C2 centre (-22.225, -25.4) radius 5.5245
  circle C3 centre (-22.225, -25.4) radius 5.1594
  circle C4 centre (-22.225, 25.4) radius 5.1594
  circle C5 centre (22.225, -25.4) radius 5.1594
  circle C6 centre (22.225, 25.4) radius 5.1594
  circle C7 centre (0, -14.8669) radius 5.1594
  arc A1 centre (30.1625, -66.8734) radius 7.9375 clockwise from (38.1, -66.8734) to (30.1625, -74.8109)
  arc A2 centre (-30.1625, -66.8734) radius 7.9375 clockwise from (-30.1625, -74.8109) to (-38.1, -66.8734)
  arc A3 centre (-30.1625, 66.8734) radius 7.9375 clockwise from (-38.1, 66.8734) to (-30.1625, 74.8109)
  arc A4 centre (30.1625, 66.8734) radius 7.9375 clockwise from (30.1625, 74.8109) to (38.1, 66.8734)
  circle C8 centre (-28.575, 65.2859) radius 3.9687
  circle C9 centre (28.575, 65.2859) radius 3.9687
  circle C10 centre (0, -62.4919) radius 3.9687
  arc A5 centre (-7.9375, 0.6112) radius 4.7625 clockwise from (-7.9375, -4.1513) to (-12.7, 0.6112)
  arc A6 centre (7.9375, 0.6112) radius 4.7625 clockwise from (12.7, 0.6112) to (7.9375, -4.1513)
  arc A7 centre (7.9375, 32.7422) radius 4.7625 clockwise from (7.9375, 37.5047) to (12.7, 32.7422)
  arc A8 centre (-7.9375, 32.7422) radius 4.7625 clockwise from (-12.7, 32.7422) to (-7.9375, 37.5047)
  circle C11 centre (22.225, -25.4) radius 3.9687
  circle C12 centre (-22.225, -25.4) radius 3.9688
  circle C13 centre (-22.225, -25.4) radius 3.9688
  circle C14 centre (22.225, 25.4) radius 3.9687
  circle C15 centre (22.225, 25.4) radius 3.9687
  circle C16 centre (-22.225, 25.4) radius 3.9687
  circle C17 centre (-22.225, 25.4) radius 3.9687
  circle C18 centre (0, 0) radius 6.35
  point P48 (28.575, -38.1)
  point P52 (28.575, -38.1)
  point P49 (-28.575, 38.1)
  point P50 (-28.575, 38.1)
  point P58 (-28.575, 0)
  point P59 (28.575, 0)
  point P60 (0, 38.1)
  point P61 (0, -38.1)
  point P62 (0, 0)
  horizontal L17
  vertical L18
  horizontal L19
  vertical L20
  coincident P48 P52
  coincident P49 P50
  midpoint L5 P58
  midpoint L18 P59
  midpoint L17 P60
  midpoint L19 P61
  midpoint L24 P62
  dimension "d123" diameter C18 = 12.7
extrude "Extrude1" new body sketch "Sketch1" profile of L3 L7 L17 L19 L21 L22 C18 against normal blind 2.54
extrude "Extrude2" add sketch "Sketch1" profile of L1 L2 L3 L4 L5 L6 L7 L8 C1 C2 C3 C4 C5 C6 C11 C12 C13 C14 C15 C16 C17 L17 L18 L19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 along normal blind 10.16
extrude "Extrude3" cut sketch "Sketch1" profile of C3 C4 C5 C6 C11 C12 C13 C14 C15 C16 C17 along normal blind 2.032
extrude "Extrude4" sketch "Sketch1" profile of C3 C4 C5 C6 C11 C12 C13 C14 C15 C16 C17 blind -3.9688 (= "( -5 / 32 ) * 1 in")
extrude "Extrude5" add sketch "Sketch1" profile of L1 L2 L8 L21 along normal blind 10.16
base_feature "Base Feature1"
position "Position4"
copy_paste_bodies "CopyPasteBodies1"
move "Move1"
copy_paste_bodies "CopyPasteBodies2"
move "Move2"
copy_paste_bodies "CopyPasteBodies3"
move "Move3"
align "Align1"
align "Align2"
align "Align3"
align "Align4"
position "Position5"
remove_body "RemoveBody1"
sketch "Sketch1" plane through (28.575, 0, 0) normal (1, 0, 0) x axis (0, 1, 0)
  line L1 (38.1, 0) -> (-38.1, 0)
  line L2 (38.1, 127) -> (38.1, 0)
  line L3 (-38.1, 127) -> (38.1, 127)
  line L4 (-38.1, 0) -> (-38.1, 127)
  circle C1 centre (0, 38.1) radius 5.8674
  circle C2 centre (0, 38.1) radius 4
  concentric C1 C2
  dimension "d135" diameter C2 = 8
extrude "Extrude1" sketch "Sketch1" profile of C2 blind 77.5
sketch "Sketch1" plane through (0, 0, 0) normal (1, 0, 0) x axis (0, 1, 0)
  line L1 (-11.475, 93.3333) -> (-16.725, 93.3333)
  line L2 (-16.725, 92.5833) -> (-11.475, 92.5833)
  line L3 (-11.475, 101.8) -> (-16.725, 101.8)
  line L4 (-16.725, 101.05) -> (-11.475, 101.05)
  line L5 (-11.475, 110.2667) -> (-16.725, 110.2667)
  line L6 (-16.725, 109.5167) -> (-11.475, 109.5167)
  line L7 (-11.475, 112.3833) -> (-16.725, 112.3833)
  line L8 (-16.725, 111.6333) -> (-11.475, 111.6333)
  line L9 (-11.475, 103.9167) -> (-16.725, 103.9167)
  line L10 (-16.725, 103.1667) -> (-11.475, 103.1667)
  line L11 (-11.475, 95.45) -> (-16.725, 95.45)
  line L12 (-16.725, 94.7) -> (-11.475, 94.7)
  line L13 (-11.475, 91.2167) -> (-16.725, 91.2167)
  line L14 (-16.725, 90.4667) -> (-11.475, 90.4667)
  line L15 (-11.475, 99.6833) -> (-16.725, 99.6833)
  line L16 (-16.725, 98.9333) -> (-11.475, 98.9333)
  line L17 (-11.475, 108.15) -> (-16.725, 108.15)
  line L18 (-16.725, 107.4) -> (-11.475, 107.4)
  line L19 (-16.725, 113.75) -> (-11.475, 113.75)
  line L20 (-11.475, 114.5) -> (-16.725, 114.5)
  line L21 (-11.475, 106.0333) -> (-16.725, 106.0333)
  line L22 (-16.725, 105.2833) -> (-11.475, 105.2833)
  line L23 (-11.475, 97.5667) -> (-16.725, 97.5667)
  line L24 (-16.725, 96.8167) -> (-11.475, 96.8167)
  line L25 (-11.475, 89.1) -> (-16.725, 89.1)
  line L26 (-16.725, 88.35) -> (-11.475, 88.35)
  line L27 (5.588, 116.84) -> (6.0357, 125.7934)
  line L28 (5.588, 58.2803) -> (5.588, 116.84)
  line L29 (-5.588, 116.84) -> (-5.588, 58.2803)
  line L30 (-6.0357, 125.7934) -> (-5.588, 116.84)
  line L31 (-38.1, 127) -> (-7.3041, 127)
  line L32 (-38.1, 0) -> (-38.1, 127)
  line L33 (38.1, 0) -> (-38.1, 0)
  line L34 (38.1, 127) -> (38.1, 0)
  line L35 (7.3041, 127) -> (38.1, 127)
  line L36 (-20.574, 15.748) -> (-20.574, 93.472)
  line L37 (-31.75, 93.472) -> (-31.75, 15.748)
  line L38 (0, 127) -> (0, 58.2803)
  line L39 (-9.671, 63.5) -> (9.671, 63.5)
  line L40 (-9.671, 101.6) -> (-9.671, 63.5)
  line L41 (9.671, 101.6) -> (-9.671, 101.6)
  line L42 (9.671, 63.5) -> (9.671, 101.6)
  line L43 (-9.671, 101.6) -> (9.671, 63.5)
  line L44 (9.671, 101.6) -> (-9.671, 63.5)
  line L45 (-9.29, 63.881) -> (9.29, 63.881)
  line L46 (-9.29, 101.219) -> (-9.29, 63.881)
  line L47 (9.29, 101.219) -> (-9.29, 101.219)
  line L48 (9.29, 63.881) -> (9.29, 101.219)
  line L49 (9.29, 88.9) -> (9.671, 91.44)
  line L50 (9.29, 63.5) -> (9.29, 88.9)
  line L51 (-9.29, 88.9) -> (-9.671, 91.44)
  line L52 (-9.29, 63.5) -> (-9.29, 88.9)
  line L53 (-5.5245, 64.135) -> (5.5245, 64.135)
  line L54 (-5.5245, 100.965) -> (-5.5245, 64.135)
  line L55 (5.5245, 100.965) -> (-5.5245, 100.965)
  line L56 (5.5245, 64.135) -> (5.5245, 100.965)
  line L57 (-5.5245, 100.965) -> (5.5245, 64.135)
  line L58 (5.5245, 100.965) -> (-5.5245, 64.135)
  line L59 (-0.3048, 95.25) -> (-0.3048, 101.6)
  arc A1 centre (-11.475, 92.9583) radius 0.375 clockwise from (-11.475, 93.3333) to (-11.475, 92.5833)
  arc A2 centre (-16.725, 92.9583) radius 0.375 clockwise from (-16.725, 92.5833) to (-16.725, 93.3333)
  arc A3 centre (-11.475, 101.425) radius 0.375 clockwise from (-11.475, 101.8) to (-11.475, 101.05)
  arc A4 centre (-16.725, 101.425) radius 0.375 clockwise from (-16.725, 101.05) to (-16.725, 101.8)
  arc A5 centre (-11.475, 109.8917) radius 0.375 clockwise from (-11.475, 110.2667) to (-11.475, 109.5167)
  arc A6 centre (-16.725, 109.8917) radius 0.375 clockwise from (-16.725, 109.5167) to (-16.725, 110.2667)
  arc A7 centre (-11.475, 112.0083) radius 0.375 clockwise from (-11.475, 112.3833) to (-11.475, 111.6333)
  arc A8 centre (-16.725, 112.0083) radius 0.375 clockwise from (-16.725, 111.6333) to (-16.725, 112.3833)
  arc A9 centre (-11.475, 103.5417) radius 0.375 clockwise from (-11.475, 103.9167) to (-11.475, 103.1667)
  arc A10 centre (-16.725, 103.5417) radius 0.375 clockwise from (-16.725, 103.1667) to (-16.725, 103.9167)
  arc A11 centre (-11.475, 95.075) radius 0.375 clockwise from (-11.475, 95.45) to (-11.475, 94.7)
  arc A12 centre (-16.725, 95.075) radius 0.375 clockwise from (-16.725, 94.7) to (-16.725, 95.45)
  arc A13 centre (-11.475, 90.8417) radius 0.375 clockwise from (-11.475, 91.2167) to (-11.475, 90.4667)
  arc A14 centre (-16.725, 90.8417) radius 0.375 clockwise from (-16.725, 90.4667) to (-16.725, 91.2167)
  arc A15 centre (-11.475, 99.3083) radius 0.375 clockwise from (-11.475, 99.6833) to (-11.475, 98.9333)
  arc A16 centre (-16.725, 99.3083) radius 0.375 clockwise from (-16.725, 98.9333) to (-16.725, 99.6833)
  arc A17 centre (-11.475, 107.775) radius 0.375 clockwise from (-11.475, 108.15) to (-11.475, 107.4)
  arc A18 centre (-16.725, 107.775) radius 0.375 clockwise from (-16.725, 107.4) to (-16.725, 108.15)
  arc A19 centre (-16.725, 114.125) radius 0.375 clockwise from (-16.725, 113.75) to (-16.725, 114.5)
  arc A20 centre (-11.475, 114.125) radius 0.375 clockwise from (-11.475, 114.5) to (-11.475, 113.75)
  arc A21 centre (-11.475, 105.6583) radius 0.375 clockwise from (-11.475, 106.0333) to (-11.475, 105.2833)
  arc A22 centre (-16.725, 105.6583) radius 0.375 clockwise from (-16.725, 105.2833) to (-16.725, 106.0333)
  arc A23 centre (-11.475, 97.1917) radius 0.375 clockwise from (-11.475, 97.5667) to (-11.475, 96.8167)
  arc A24 centre (-16.725, 97.1917) radius 0.375 clockwise from (-16.725, 96.8167) to (-16.725, 97.5667)
  arc A25 centre (-11.475, 88.725) radius 0.375 clockwise from (-11.475, 89.1) to (-11.475, 88.35)
  arc A26 centre (-16.725, 88.725) radius 0.375 clockwise from (-16.725, 88.35) to (-16.725, 89.1)
  circle C1 centre (0, 38.1) radius 11.049
  arc A27 centre (7.3041, 125.73) radius 1.27 clockwise from (6.0357, 125.7934) to (7.3041, 127)
  arc A28 centre (0, 58.2803) radius 5.588 clockwise from (5.588, 58.2803) to (-5.588, 58.2803)
  arc A29 centre (-7.3041, 125.73) radius 1.27 clockwise from (-7.3041, 127) to (-6.0357, 125.7934)
  arc A30 centre (-26.162, 15.748) radius 5.588 clockwise from (-20.574, 15.748) to (-31.75, 15.748)
  arc A31 centre (-26.162, 93.472) radius 5.588 clockwise from (-31.75, 93.472) to (-20.574, 93.472)
  circle C2 centre (0, 69.6595) radius 3.9687
  circle C3 centre (-5.226, 95.25) radius 2.3813
  circle C4 centre (-5.226, 95.25) radius 4.9213
  circle C5 centre (0, 69.6595) radius 5.5245
  point P87 (0, 58.2803)
  point P102 (0, 58.2803)
  point P108 (0, 82.55)
  point P113 (9.671, 91.44)
  point P114 (9.29, 88.9)
  point P115 (9.29, 63.5)
  point P116 (-9.671, 91.44)
  point P117 (-9.29, 88.9)
  point P118 (-9.29, 63.5)
  point P123 (0, 82.55)
  point P124 (0, 69.6595)
  point P127 (-0.3048, 101.6)
  point P128 (-0.3048, 95.25)
  point P129 (0, 69.6595)
  point P106 (-9.671, 101.6)
  point P107 (9.671, 101.6)
  point P105 (-9.671, 63.5)
  point P121 (-5.5245, 100.965)
  point P122 (5.5245, 100.965)
  point P120 (-5.5245, 64.135)
  point P125 (-5.226, 95.25)
  coincident P87 P102
  vertical L38
  horizontal L39
  perpendicular L39 L40
  parallel L39 L41
  parallel L40 L42
  coincident L43 P108
  coincident L44 P108
  coincident L38 P108
  coincident L42 P113
  coincident L48 P114
  coincident L39 P115
  perpendicular L39 L50
  symmetric L38 P113 P116
  symmetric L38 P114 P117
  symmetric L38 P115 P118
  horizontal L53
  perpendicular L53 L54
  parallel L53 L55
  parallel L54 L56
  coincident L57 P123
  coincident L58 P123
  coincident P108 P123
  coincident L38 P124
  coincident L41 P127
  perpendicular L47 L59
  tangent C4 L59
  coincident C4 P128
  coincident L38 P129
  tangent L53 C5
  coincident P124 P129
  dimension "d139" distance P106 P107 = 19.3421
  dimension "d140" distance P105 P106 = 38.1
  dimension "d141" = 0.381
  dimension "d142" distance L35 L41 = 25.4
  dimension "d143" distance P107 P113 = 10.16
  dimension "d144" distance P107 P114 = 12.7
  dimension "d145" distance P121 P122 = 11.049
  dimension "d146" distance P120 P121 = 36.83
  dimension "d147" diameter C2 = 7.9375
  dimension "d149" diameter C3 = 4.7625
  dimension "d150" distance L40 P125 = 4.445
  dimension "d151" distance L41 P125 = 6.35
  dimension "d152" = 2.54
  dimension "d153" diameter C5 = 11.049
extrude "Extrude1" sketch "Sketch1" profile of L39 L40 L41 L42 L49 L50 L51 L52 L53 L54 L55 L56 C2 C3 C4 L59 C5 to an object bodies "Wheel Block"
extrude "Extrude2" sketch "Sketch1" profile of L54 L55 L56 C2 C4 L59 C5 blind 3.175
extrude "Extrude3" of existing geometry blind -3.175
sketch "Sketch2" plane through (-19.05, 0, 0) normal (-1, 0, 0) x axis (0, -1, 0)
  line L1 (0.3048, 100.965) -> (0.3048, 95.25)
  line L2 (-5.5245, 100.965) -> (0.3048, 100.965)
  line L3 (-5.5245, 69.6595) -> (-5.5245, 100.965)
  line L4 (5.5245, 90.3378) -> (5.5245, 69.6595)
  circle C1 centre (0, 69.6595) radius 3.9687
  arc A1 centre (0, 69.6595) radius 5.5245 clockwise from (5.5245, 69.6595) to (-5.5245, 69.6595)
  arc A2 centre (5.226, 95.25) radius 4.9213 clockwise from (5.5245, 90.3378) to (0.3048, 95.25)
  circle C2 centre (0, 69.6595) radius 3.9688
  circle C3 centre (5.226, 95.25) radius 2.2225
  concentric C1 C2
  concentric A2 C3
  dimension "d163" diameter C2 = 7.9375 (= "( 5 / 16 ) * 1 in")
  dimension "d166" diameter C3 = 4.445
extrude "Extrude4" new body sketch "Sketch2" profile of C1 C2 against normal blind 31.75 bodies "Wheel Pin"
move "Move1"
extrude "Extrude5" sketch "Sketch2" profile of C3 to an object bodies "Locking Pin"
sketch "Sketch3" plane through (0, -9.671, 0) normal (0, -1, 0) x axis (1, 0, 0)
  line L1 (15.875, 101.6) -> (15.875, 91.44)
  line L2 (-15.875, 101.6) -> (15.875, 101.6)
  line L3 (-15.875, 91.44) -> (-15.875, 101.6)
  line L4 (15.875, 91.44) -> (-15.875, 91.44)
  line L5 (-19.05, 64.135) -> (-19.05, 69.6595)
  line L6 (-19.05, 69.6595) -> (-19.05, 100.965)
  line L7 (-19.05, 100.965) -> (-15.875, 100.965)
  line L8 (19.05, 100.965) -> (15.875, 100.965)
  line L9 (19.05, 100.965) -> (19.05, 69.6595)
  line L10 (19.05, 69.6595) -> (19.05, 64.135)
  line L11 (15.875, 64.135) -> (15.875, 63.5)
  line L12 (15.875, 63.5) -> (-15.875, 63.5)
  line L13 (-15.875, 63.5) -> (-15.875, 64.135)
  line L14 (15.875, 101.6) -> (-15.875, 101.6)
  line L15 (15.875, 101.6) -> (15.875, 100.965)
  line L16 (-15.875, 100.965) -> (-15.875, 101.6)
  line L17 (-19.05, 64.135) -> (-15.875, 64.135)
  line L18 (19.05, 64.135) -> (15.875, 64.135)
  line L19 (0, 63.5) -> (0, 101.6)
  line L20 (-5.3086, 57.15) -> (5.3086, 57.15)
  line L21 (-5.3086, 107.95) -> (-5.3086, 57.15)
  line L22 (5.3086, 107.95) -> (-5.3086, 107.95)
  line L23 (5.3086, 57.15) -> (5.3086, 107.95)
  line L24 (-5.3086, 107.95) -> (5.3086, 57.15)
  line L25 (5.3086, 107.95) -> (-5.3086, 57.15)
  line L26 (19.05, 88.9) -> (-19.05, 88.9)
  circle C1 centre (0, 83.5914) radius 5.3086
  point P20 (0, 101.6)
  point P21 (0, 63.5)
  point P26 (0, 82.55)
  point P27 (0, 83.5914)
  point P28 (-19.05, 88.9)
  point P29 (19.05, 88.9)
  point P24 (-5.3086, 107.95)
  point P25 (5.3086, 107.95)
  point P23 (-5.3086, 57.15)
  midpoint L14 P20
  midpoint L12 P21
  horizontal L20
  perpendicular L20 L21
  parallel L20 L22
  parallel L21 L23
  coincident L24 P26
  coincident L25 P26
  midpoint L19 P26
  coincident L19 P27
  coincident L6 P28
  coincident L9 P29
  perpendicular L9 L26
  tangent C1 L26
  dimension "d170" distance P24 P25 = 10.6172
  dimension "d171" distance P23 P24 = 50.8
  dimension "d172" diameter C1 = 10.6172
  dimension "d173" distance L14 L26 = 12.7
extrude "Extrude6" cut sketch "Sketch3" profile of L12 L21 L23 C1 against normal blind 19.3548
fillet "Fillet1" radius 3.175
fillet "Fillet2" radius 1.27
extrude "Extrude7" cut sketch "Sketch1" profile of C18 against normal blind 40.64
extrude "Extrude8" sketch "Sketch1" profile of C18 blind 76.2 bodies "Wheel Screw"
thread "Thread1"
